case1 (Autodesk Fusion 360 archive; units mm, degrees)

design "case" references "ptb6043-2010bp", "5V2AACDC", "xiaodmx", "nac3mpxxa", "3-D NC5FAH"
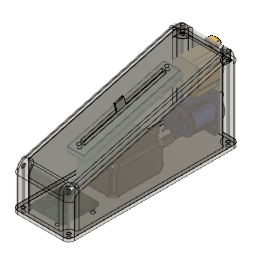
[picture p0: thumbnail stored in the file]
sketch "Sketch1" plane through (0, 0, 0) normal (0, 0, 1) x axis (1, 0, 0)
  line L1 (-25.2326, 75) -> (24.7674, 75)
  line L2 (-25.2326, -75) -> (-25.2326, 75)
  line L3 (24.7674, -75) -> (-25.2326, -75)
  line L4 (24.7674, 75) -> (24.7674, -75)
  line L5 (-25.2326, -75) -> (24.7674, 75)
  line L6 (24.7674, -75) -> (-25.2326, 75)
  point P6 (-0.2326, 0)
  point P4 (-25.2326, -75)
  point P5 (24.7674, -75)
  point P3 (-25.2326, 75)
  horizontal L1
  perpendicular L1 L2
  parallel L1 L3
  parallel L2 L4
  coincident L5 P6
  coincident L6 P6
  dimension "d1" distance P4 P5 = 50
  dimension "d2" distance P3 P4 = 150
extrude "Extrude1" new body sketch "Sketch1" profile of L1 L2 L3 L4 along normal blind 75
chamfer "Chamfer1" distance 150 Rotate Angle 15
fillet "Fillet1" radius 10 10
fillet "Fillet2" radius 5
sketch "Sketch2" plane through (0, -13.726, 51.226) normal (0, -0.2588, 0.9659) x axis (1, 0, 0)
  line L1 (19.7674, 78.8236) -> (19.7674, -55.7623)
  line L2 (-20.2326, 78.8236) -> (19.7674, 78.8236)
  line L3 (-20.2326, -55.7623) -> (-20.2326, 78.8236)
  line L4 (19.7674, -55.7623) -> (-20.2326, -55.7623)
  line L5 (19.7674, -55.7623) -> (-20.2326, 78.8236)
  line L6 (-20.2326, -55.7623) -> (19.7674, 78.8236)
  point P4 (-20.2326, 78.8236)
  point P6 (-20.2326, 78.8236)
  point P2 (19.7674, -55.7623)
  point P7 (19.7674, -55.7623)
  point P3 (19.7674, 78.8236)
  point P8 (19.7674, 78.8236)
  point P5 (-20.2326, -55.7623)
  point P9 (-20.2326, -55.7623)
  point P10 (-0.2326, 11.5307)
  coincident P4 P6
  coincident P2 P7
  coincident P3 P8
  coincident P5 P9
  midpoint L6 P10
shell "Shell1" innerThickness 3
component_from_bodies "ボディ -> コンポーネント"
component_insert "Component Insert1"
joint "Assemble" alignAngle 90 alignOffsetX 0 alignOffsetY 0 alignOffsetZ 0
sketch "Sketch3" plane through (0.2736, -1.8193, 51.3105) normal (0, -0.2588, 0.9659) x axis (-1, 0, 0)
  line L1 (-6.3438, -43.7578) -> (-6.3438, -43.5578)
  line L2 (7.3562, -43.7578) -> (-6.3438, -43.7578)
  line L3 (7.3562, -43.5578) -> (7.3562, -43.7578)
  line L4 (7.5562, -43.5578) -> (7.3562, -43.5578)
  line L5 (7.5562, 43.5422) -> (7.5562, -43.5578)
  line L6 (7.3562, 43.5422) -> (7.5562, 43.5422)
  line L7 (7.3562, 43.7422) -> (7.3562, 43.5422)
  line L8 (-6.3438, 43.7422) -> (7.3562, 43.7422)
  line L9 (-6.3438, 43.5422) -> (-6.3438, 43.7422)
  line L10 (-6.5438, 43.5422) -> (-6.3438, 43.5422)
  line L11 (-6.5438, -43.5578) -> (-6.5438, 43.5422)
  line L12 (-6.3438, -43.5578) -> (-6.5438, -43.5578)
  line L13 (-0.9188, -37.0078) -> (1.9312, -37.0078)
  line L14 (-0.9188, 36.9922) -> (-0.9188, -37.0078)
  line L15 (1.9312, 36.9922) -> (-0.9188, 36.9922)
  line L16 (1.9312, -37.0078) -> (1.9312, 36.9922)
  line L17 (1.9312, -37.0078) -> (-0.9188, 36.9922)
  line L18 (-0.9188, -37.0078) -> (1.9312, 36.9922)
  line L19 (-0.9188, -37.0078) -> (1.9312, -37.0078)
  line L20 (-0.9188, 36.9922) -> (1.9312, 36.9922)
  line L21 (-0.9188, -37.0078) -> (-0.9188, 36.9922)
  line L22 (1.9312, 36.9922) -> (1.9312, -37.0078)
  circle C1 centre (0.5062, -40.0078) radius 1.25
  circle C2 centre (0.5062, 39.9922) radius 1.25
  circle C3 centre (0.5062, -40.0078) radius 1.5
  circle C4 centre (0.5062, 39.9922) radius 1.5
  point P18 (-0.9188, 36.9922)
  point P20 (-0.9188, 36.9922)
  point P16 (1.9312, -37.0078)
  point P21 (1.9312, -37.0078)
  point P19 (1.9312, 36.9922)
  point P22 (1.9312, 36.9922)
  point P17 (-0.9188, -37.0078)
  point P23 (-0.9188, -37.0078)
  point P24 (0.5062, -0.0078)
  coincident P18 P20
  coincident P16 P21
  coincident P19 P22
  coincident P17 P23
  coincident L18 P24
  coincident L17 P24
  concentric C1 C3
  concentric C2 C4
  dimension "d22" diameter C3 = 3
  dimension "d23" diameter C4 = 3
extrude "Extrude1" cut sketch "Sketch3" profile of C1 C2 L13 L14 L15 L16 L17 L18 L19 L20 L21 L22 C3 C4 along normal blind 10
component_insert "Component Insert2"
step "GeometricRelationship1"
step "GeometricRelationship2" Offset 0
component_insert "Component Insert3"
step "GeometricRelationship3"
step "GeometricRelationship4" Offset 0
position "Position1"
sketch "Sketch6" plane through (0, 66.1549, 0) normal (0, -1, 0) x axis (1, 0, 0)
  line L1 (31, -12.7756) -> (-9, -12.7756)
  line L2 (31, 49.1922) -> (31, -12.7756)
  line L3 (-9, 49.1922) -> (31, 49.1922)
  line L4 (-9, -12.7756) -> (-9, 49.1922)
  circle C1 centre (11, 3.8312) radius 12
  circle C2 centre (11, 3.8312) radius 11.509
  circle C3 centre (20.5, 15.8312) radius 1.5
  circle C4 centre (20.5, 15.8312) radius 1.7227
  circle C5 centre (1.5, -8.1688) radius 1.5
  circle C6 centre (1.5, -8.1688) radius 1.7227
  circle C7 centre (11, 36.1664) radius 11.1
  arc A1 centre (11, 36.1664) radius 9.75 clockwise from (13.5, 45.5904) to (8.5, 45.5904)
  circle C8 centre (20.9, 46.0664) radius 1.5
  circle C9 centre (20.9, 46.0664) radius 1.175
  circle C10 centre (1.1, 26.2664) radius 1.5
  circle C11 centre (1.1, 26.2664) radius 1.175
  concentric C1 C2
  concentric C3 C4
  concentric C5 C6
  concentric C7 A1
  concentric C8 C9
  concentric C10 C11
  dimension "d28" diameter C1 = 24
  dimension "d29" diameter C3 = 3
  dimension "d30" diameter C5 = 3
  dimension "d31" diameter C7 = 22.2
  dimension "d32" diameter C8 = 3
  dimension "d33" diameter C10 = 3
extrude "Extrude2" cut sketch "Sketch6" profile of C1 C2 C3 C5 C7 C8 C9 C10 C11 against normal blind 60
sketch "Sketch7" plane through (0, 0, -12.7756) normal (0, 0, -1) x axis (1, 0, 0)
  line L1 (33, -64.1549) -> (33, 75.8451)
  line L2 (-9, -66.1549) -> (31, -66.1549)
  line L3 (-11, 75.8451) -> (-11, -64.1549)
  line L4 (31, 77.8451) -> (-9, 77.8451)
  line L5 (36, 75.8451) -> (36, -64.1549)
  line L6 (-9, 80.8451) -> (31, 80.8451)
  line L7 (-14, -64.1549) -> (-14, 75.8451)
  line L8 (31, -69.1549) -> (-9, -69.1549)
  line L9 (-9, 75.8451) -> (-12.5355, 79.3806)
  line L10 (31, 75.8451) -> (34.5355, 79.3806)
  line L11 (31, -64.1549) -> (34.5355, -67.6905)
  line L12 (-9, -64.1549) -> (-12.5355, -67.6905)
  arc A1 centre (31, -64.1549) radius 2 clockwise from (33, -64.1549) to (31, -66.1549)
  arc A2 centre (-9, -64.1549) radius 2 clockwise from (-9, -66.1549) to (-11, -64.1549)
  arc A3 centre (-9, 75.8451) radius 2 clockwise from (-11, 75.8451) to (-9, 77.8451)
  arc A4 centre (31, 75.8451) radius 2 clockwise from (31, 77.8451) to (33, 75.8451)
  arc A5 centre (31, -64.1549) radius 5 clockwise from (36, -64.1549) to (31, -69.1549)
  arc A6 centre (31, 75.8451) radius 5 clockwise from (31, 80.8451) to (36, 75.8451)
  arc A7 centre (-9, 75.8451) radius 5 clockwise from (-14, 75.8451) to (-9, 80.8451)
  arc A8 centre (-9, -64.1549) radius 5 clockwise from (-9, -69.1549) to (-14, -64.1549)
  circle C1 centre (-9, 75.8451) radius 1.2
  circle C2 centre (31, 75.8451) radius 1.2
  circle C3 centre (-9, -64.1549) radius 1.2
  circle C4 centre (31, -64.1549) radius 1.2
  circle C5 centre (-9, 75.8451) radius 5
  circle C6 centre (31, 75.8451) radius 5
  circle C7 centre (31, -64.1549) radius 5
  circle C8 centre (-9, -64.1549) radius 5
  point P22 (-12.5355, 79.3806)
  point P11 (-9, 75.8451)
  point P23 (-9, 75.8451)
  point P24 (34.5355, 79.3806)
  point P13 (31, 75.8451)
  point P25 (31, 75.8451)
  point P26 (34.5355, -67.6905)
  point P5 (31, -64.1549)
  point P27 (31, -64.1549)
  point P28 (-12.5355, -67.6905)
  point P8 (-9, -64.1549)
  point P29 (-9, -64.1549)
  point P30 (-9, 75.8451)
  point P33 (31, -64.1549)
  point P34 (-9, 75.8451)
  point P35 (31, 75.8451)
  point P36 (31, -64.1549)
  midpoint A7 P22
  coincident P11 P23
  midpoint A6 P24
  coincident P13 P25
  midpoint A5 P26
  coincident P5 P27
  midpoint A8 P28
  coincident P8 P29
  coincident P23 P30
  concentric A4 C2
  concentric A2 C3
  coincident P27 P33
  coincident P23 P34
  coincident P22 C5
  coincident P25 P35
  coincident P27 P36
  coincident P26 C7
  concentric C3 C8
  coincident P28 C8
  dimension "d38" diameter C1 = 2.4
  dimension "d39" diameter C2 = 2.4
  dimension "d40" diameter C3 = 2.4
  dimension "d41" diameter C4 = 2.4
extrude "Extrude3" add sketch "Sketch7" profile of L1 L3 A3 L4 A4 C1 C2 C5 C6 to an object
extrude "Extrude6" add sketch "Sketch7" profile of L1 A1 L2 A2 L3 C3 C4 C7 C8 against normal blind 61.9
fillet "Fillet2" radius 1.8 1.8
extrude "Extrude4" new body of existing geometry blind 7.2
copy_paste_bodies "CutPasteBodies"
component_insert "Component Insert4"
component_insert "Component Insert5"
sketch "Sketch8" plane through (0, 0, -12.7756) normal (0, 0, -1) x axis (1, 0, 0)
  line L1 (33, -57.3579) -> (33, 69.048)
  line L2 (-2.2029, -66.1549) -> (24.2029, -66.1549)
  line L3 (-11, 69.048) -> (-11, -57.3579)
  line L4 (24.2029, 77.8451) -> (-2.2029, 77.8451)
  line L5 (36, 75.8451) -> (36, -64.1549)
  line L6 (-9, 80.8451) -> (31, 80.8451)
  line L7 (-14, -64.1549) -> (-14, 75.8451)
  line L8 (31, -69.1549) -> (-9, -69.1549)
  circle C1 centre (31, -64.1549) radius 1.2
  circle C2 centre (-9, -64.1549) radius 1.2
  circle C3 centre (-9, 75.8451) radius 1.2
  circle C4 centre (31, 75.8451) radius 1.2
  arc A1 centre (31.2, -57.3579) radius 1.8 clockwise from (33, -57.3579) to (31.1471, -59.1571)
  arc A2 centre (31, -64.1549) radius 5 clockwise from (26.0022, -64.302) to (31.1471, -59.1571)
  arc A3 centre (24.2029, -64.3549) radius 1.8 clockwise from (26.0022, -64.302) to (24.2029, -66.1549)
  arc A4 centre (-2.2029, -64.3549) radius 1.8 clockwise from (-2.2029, -66.1549) to (-4.0022, -64.302)
  arc A5 centre (-9, -64.1549) radius 5 clockwise from (-9.1471, -59.1571) to (-4.0022, -64.302)
  arc A6 centre (-9.2, -57.3579) radius 1.8 clockwise from (-9.1471, -59.1571) to (-11, -57.3579)
  arc A7 centre (-9.2, 69.048) radius 1.8 clockwise from (-11, 69.048) to (-9.1471, 70.8472)
  arc A8 centre (-9, 75.8451) radius 5 clockwise from (-4.0022, 75.9921) to (-9.1471, 70.8472)
  arc A9 centre (-2.2029, 76.0451) radius 1.8 clockwise from (-4.0022, 75.9921) to (-2.2029, 77.8451)
  arc A10 centre (24.2029, 76.0451) radius 1.8 clockwise from (24.2029, 77.8451) to (26.0022, 75.9921)
  arc A11 centre (31, 75.8451) radius 5 clockwise from (31.1471, 70.8472) to (26.0022, 75.9921)
  arc A12 centre (31.2, 69.048) radius 1.8 clockwise from (31.1471, 70.8472) to (33, 69.048)
  arc A13 centre (31, -64.1549) radius 5 clockwise from (36, -64.1549) to (31, -69.1549)
  arc A14 centre (31, 75.8451) radius 5 clockwise from (31, 80.8451) to (36, 75.8451)
  arc A15 centre (-9, 75.8451) radius 5 clockwise from (-14, 75.8451) to (-9, 80.8451)
  arc A16 centre (-9, -64.1549) radius 5 clockwise from (-9, -69.1549) to (-14, -64.1549)
extrude "Extrude7" new body sketch "Sketch8" along normal blind 3
sketch "Sketch9" plane through (0, 0, -8.44) normal (0, 0, 1) x axis (-1, 0, 0)
  line L1 (-25.3494, 73.1672) -> (-25.3469, 73.3101)
  line L2 (-25.3494, 45.1886) -> (-25.3494, 73.1672)
  line L3 (-25.3469, 45.0457) -> (-25.3494, 45.1886)
  line L4 (-23.3494, 43.1886) -> (-23.4923, 43.1911)
  line L5 (1.6828, 43.1886) -> (-23.3494, 43.1886)
  line L6 (1.8257, 43.1911) -> (1.6828, 43.1886)
  line L7 (3.6828, 45.1886) -> (3.6803, 45.0457)
  line L8 (3.6828, 73.1672) -> (3.6828, 45.1886)
  line L9 (3.6803, 73.3101) -> (3.6828, 73.1672)
  line L10 (1.6828, 75.1672) -> (1.8257, 75.1647)
  line L11 (-23.3494, 75.1672) -> (1.6828, 75.1672)
  line L12 (-23.4923, 75.1647) -> (-23.3494, 75.1672)
  arc A1 centre (-23.3494, 73.1672) radius 2.0026 clockwise from (-25.3469, 73.3101) to (-23.4923, 75.1647)
  arc A2 centre (-23.3494, 45.1886) radius 2.0026 clockwise from (-23.4923, 43.1911) to (-25.3469, 45.0457)
  arc A3 centre (1.6828, 45.1886) radius 2.0026 clockwise from (3.6803, 45.0457) to (1.8257, 43.1911)
  arc A4 centre (1.6828, 73.1672) radius 2.0026 clockwise from (1.8257, 75.1647) to (3.6803, 73.3101)
  circle C1 centre (-22.276, 46.262) radius 1.5875
  circle C2 centre (0.584, 46.262) radius 1.5875
  circle C3 centre (-11.058, 47.85) radius 0.3374
  circle C4 centre (-4.75, 47.85) radius 0.3374
  circle C5 centre (-11.058, 49.85) radius 0.3374
  circle C6 centre (-4.75, 49.85) radius 0.3374
  circle C7 centre (1.6, 51.406) radius 0.3374
  circle C8 centre (-11.058, 51.85) radius 0.3374
  circle C9 centre (-4.75, 51.85) radius 0.3374
  circle C10 centre (1.6, 53.406) radius 0.3374
  circle C11 centre (1.6, 55.406) radius 0.3374
  circle C12 centre (-23.8, 56.93) radius 0.4874
  circle C13 centre (-21.26, 56.93) radius 0.4874
  circle C14 centre (-6.02, 56.93) radius 0.4874
  circle C15 centre (-3.48, 56.93) radius 0.4874
  circle C16 centre (-17.44, 56.92) radius 0.3874
  circle C17 centre (-9.82, 56.92) radius 0.3874
  circle C18 centre (-23.8, 59.47) radius 0.4874
  circle C19 centre (-21.26, 59.47) radius 0.4874
  circle C20 centre (-6.02, 59.47) radius 0.4874
  circle C21 centre (-3.48, 59.47) radius 0.4874
  circle C22 centre (-17.44, 59.46) radius 0.3874
  circle C23 centre (-9.82, 59.46) radius 0.3874
  circle C24 centre (1.6, 60.232) radius 0.4874
  circle C25 centre (-23.8, 62.01) radius 0.4874
  circle C26 centre (-21.26, 62.01) radius 0.4874
  circle C27 centre (-6.02, 62.01) radius 0.4874
  circle C28 centre (-3.48, 62.01) radius 0.4874
  circle C29 centre (-17.44, 62) radius 0.3874
  circle C30 centre (-9.82, 62) radius 0.3874
  circle C31 centre (1.6, 62.772) radius 0.4874
  circle C32 centre (-23.8, 64.55) radius 0.4874
  circle C33 centre (-21.26, 64.55) radius 0.4874
  circle C34 centre (-6.02, 64.55) radius 0.4874
  circle C35 centre (-3.48, 64.55) radius 0.4874
  circle C36 centre (-17.44, 64.54) radius 0.3874
  circle C37 centre (-9.82, 64.54) radius 0.3874
  circle C38 centre (-0.94, 67.066) radius 0.4874
  circle C39 centre (1.6, 67.066) radius 0.4874
  circle C40 centre (-23.8, 67.09) radius 0.4874
  circle C41 centre (-21.26, 67.09) radius 0.4874
  circle C42 centre (-6.02, 67.09) radius 0.4874
  circle C43 centre (-3.48, 67.09) radius 0.4874
  circle C44 centre (-0.94, 69.606) radius 0.4874
  circle C45 centre (1.6, 69.606) radius 0.4874
  circle C46 centre (-23.8, 69.63) radius 0.4874
  circle C47 centre (-21.26, 69.63) radius 0.4874
  circle C48 centre (-6.02, 69.63) radius 0.4874
  circle C49 centre (-3.48, 69.63) radius 0.4874
  circle C50 centre (-16.18, 70.9) radius 1.5875
  circle C51 centre (-0.94, 72.146) radius 0.4874
  circle C52 centre (1.6, 72.146) radius 0.4874
  circle C53 centre (-23.8, 72.17) radius 0.4874
  circle C54 centre (-21.26, 72.17) radius 0.4874
  circle C55 centre (-6.02, 72.17) radius 0.4874
  circle C56 centre (-3.48, 72.17) radius 0.4874
  point P22 (-22.276, 46.262)
  point P23 (0.584, 46.262)
  point P71 (-16.18, 70.9)
  dimension "d68" angle P22 P23 P71 = 76.103
extrude "Extrude8" cut sketch "Sketch9" profile of C1 C2 C50 against normal blind 10
sketch "Sketch10" plane through (0, 0, -12.7756) normal (0, 0, 1) x axis (-1, 0, 0)
  line L1 (9, -69.1549) -> (-31, -69.1549)
  line L2 (14, 75.8451) -> (14, -64.1549)
  line L3 (-31, 80.8451) -> (9, 80.8451)
  line L4 (-36, -64.1549) -> (-36, 75.8451)
  arc A1 centre (9, -64.1549) radius 5 clockwise from (14, -64.1549) to (9, -69.1549)
  arc A2 centre (9, 75.8451) radius 5 clockwise from (9, 80.8451) to (14, 75.8451)
  arc A3 centre (-31, 75.8451) radius 5 clockwise from (-36, 75.8451) to (-31, 80.8451)
  arc A4 centre (-31, -64.1549) radius 5 clockwise from (-31, -69.1549) to (-36, -64.1549)
  circle C1 centre (-31, -64.1549) radius 1.2
  circle C2 centre (-31, 75.8451) radius 1.2
  circle C3 centre (9, -64.1549) radius 1.2
  circle C4 centre (9, 75.8451) radius 1.2
  circle C5 centre (-16.18, 70.9) radius 1.5875
  circle C6 centre (-22.276, 46.262) radius 1.5875
  circle C7 centre (0.584, 46.262) radius 1.5875
  circle C8 centre (9, -64.1549) radius 1.5
  circle C9 centre (-31, -64.1549) radius 1.5
  circle C10 centre (9, 75.8451) radius 1.5
  circle C11 centre (-31, 75.8451) radius 1.5
  concentric A1 C8
  concentric A4 C9
  concentric A2 C10
  concentric A3 C11
  dimension "d69" diameter C8 = 3
  dimension "d70" diameter C9 = 3
  dimension "d71" diameter C10 = 3
  dimension "d72" diameter C11 = 3
extrude "Extrude9" cut sketch "Sketch10" profile of C1 C2 C3 C4 C8 C9 C10 C11 against normal blind 10
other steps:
base_feature "基準フィーチャ"
base_feature "Base Feature"
create_component "CreateComponent3"
reparent_decal "デカールを再ペアレント化"
remove_body "RemoveBody2"
joint_origin "JointOrigin2"
reparent_decal "ReparentDecal3"
remove_body "RemoveBody3"
reparent_decal "ReparentDecal4"
remove_body "RemoveBody4"

design "5V2AACDC"
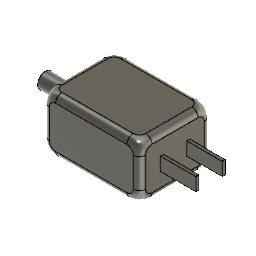
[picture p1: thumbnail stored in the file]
sketch "Sketch1" plane through (0, 0, 0) normal (0, 0, 1) x axis (1, 0, 0)
  line L1 (-23, 17) -> (23, 17)
  line L2 (-23, -17) -> (-23, 17)
  line L3 (23, -17) -> (-23, -17)
  line L4 (23, 17) -> (23, -17)
  line L5 (-23, -17) -> (23, 17)
  line L6 (23, -17) -> (-23, 17)
  point P6 (0, 0)
  point P1 (0, 0)
  point P4 (-23, -17)
  point P5 (23, -17)
  point P3 (-23, 17)
  horizontal L1
  perpendicular L1 L2
  parallel L1 L3
  parallel L2 L4
  coincident L5 P6
  coincident L6 P6
  coincident P1 P6
  dimension "d3" distance P4 P5 = 46
  dimension "d4" distance P3 P4 = 34
extrude "Extrude1" new body sketch "Sketch1" profile of L1 L2 L3 L4 along normal blind 26
sketch "Sketch2" plane through (-23, 0, 0) normal (-1, 0, 0) x axis (0, -1, 0)
  line L1 (17, 0) -> (-17, 0)
  line L2 (17, 26) -> (17, 0)
  line L3 (-17, 26) -> (17, 26)
  line L4 (-17, 0) -> (-17, 26)
  circle C1 centre (0, 13) radius 3.75
  dimension "d5" diameter C1 = 7.5
extrude "Extrude2" add sketch "Sketch2" profile of C1 along normal blind 16
sketch "Sketch3" plane through (23, 0, 0) normal (1, 0, 0) x axis (0, 1, 0)
  line L1 (17, 0) -> (-17, 0)
  line L2 (17, 26) -> (17, 0)
  line L3 (-17, 26) -> (17, 26)
  line L4 (-17, 0) -> (-17, 26)
  line L5 (-7.05, 16.175) -> (7.05, 16.175)
  line L6 (-7.05, 9.825) -> (-7.05, 16.175)
  line L7 (7.05, 9.825) -> (-7.05, 9.825)
  line L8 (7.05, 16.175) -> (7.05, 9.825)
  line L9 (-7.05, 9.825) -> (7.05, 16.175)
  line L10 (7.05, 9.825) -> (-7.05, 16.175)
  line L11 (-5.55, 16.175) -> (-7.05, 16.175)
  line L12 (-5.55, 9.825) -> (-5.55, 16.175)
  line L13 (-7.05, 9.825) -> (-5.55, 9.825)
  line L14 (-7.05, 16.175) -> (-7.05, 9.825)
  line L15 (5.55, 16.175) -> (7.05, 16.175)
  line L16 (5.55, 9.825) -> (5.55, 16.175)
  line L17 (7.05, 9.825) -> (5.55, 9.825)
  line L18 (7.05, 16.175) -> (7.05, 9.825)
  point P10 (0, 13)
  point P8 (-7.05, 9.825)
  point P9 (7.05, 9.825)
  point P7 (-7.05, 16.175)
  point P11 (-5.55, 16.175)
  point P6 (7.05, 16.175)
  point P14 (5.55, 16.175)
  horizontal L5
  perpendicular L5 L6
  parallel L5 L7
  parallel L6 L8
  coincident L9 P10
  coincident L10 P10
  horizontal L11
  vertical L12
  horizontal L13
  vertical L14
  horizontal L15
  vertical L16
  horizontal L17
  vertical L18
  dimension "d8" distance P8 P9 = 14.1
  dimension "d9" distance P7 P8 = 6.35
  dimension "d10" distance P7 P11 = 1.5
  dimension "d11" distance P6 P14 = 1.5
extrude "Extrude3" add sketch "Sketch3" profile of L11 L12 L13 L14 L15 L16 L17 L18 along normal blind 17
fillet "Fillet1" radius 3

design "ptb6043-2010bp"
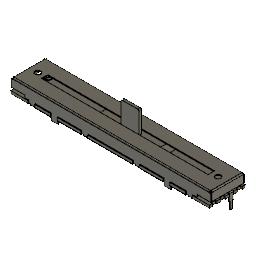
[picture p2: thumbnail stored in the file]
description: Part Number
part number: PTB6043-2010BP
base_feature "Base Feature"
move "Move1" RotateAngle 90

design "3-D NC5FAH"
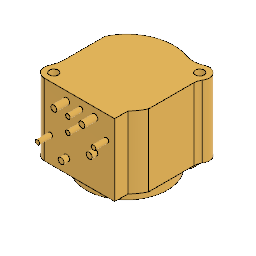
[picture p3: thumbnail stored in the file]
description: Part Number
part number: D-NC5FAH
base_feature "Base Feature"

design "nac3mpxxa"
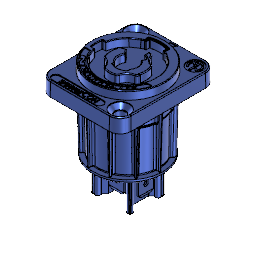
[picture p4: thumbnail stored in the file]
description: Part Number
part number: NAC3MPXXA
base_feature "Base Feature"

design "xiaodmx"
description: KiCad electronic assembly
part number: xiaodmx 1
description: Part Number
part number: xiaodmx 1.2.1
part number: xiaodmx 1.2.2
part number: PinHeader-01x07_P2.54mm_Vertical_THT
part number: xiaodmx 1.5.1
part number: xiaodmx 1.5.2
part number: PinHeader-01x02_P2.54mm_Vertical_THT
part number: xiaodmx 1.6.1
part number: xiaodmx 1.6.2
part number: xiaodmx 1.6.3
base_feature "Base Feature1"
base_feature "Base Feature1"
base_feature "Base Feature1"
base_feature "Base Feature1"
base_feature "Base Feature1"
base_feature "Base Feature1"
base_feature "Base Feature1"
base_feature "Base Feature1"
base_feature "Base Feature1"
base_feature "Base Feature1"
base_feature "Base Feature1"
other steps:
create_component "CreateComponent1"
create_component "CreateComponent2"
create_component "CreateComponent1"
create_component "CreateComponent2"
create_component "CreateComponent3"
create_component "CreateComponent1"
create_component "CreateComponent2"
create_component "CreateComponent4"
create_component "CreateComponent1"
create_component "CreateComponent2"
create_component "CreateComponent3"
create_component "CreateComponent5"
create_component "CreateComponent6"
create_component "CreateComponent7"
